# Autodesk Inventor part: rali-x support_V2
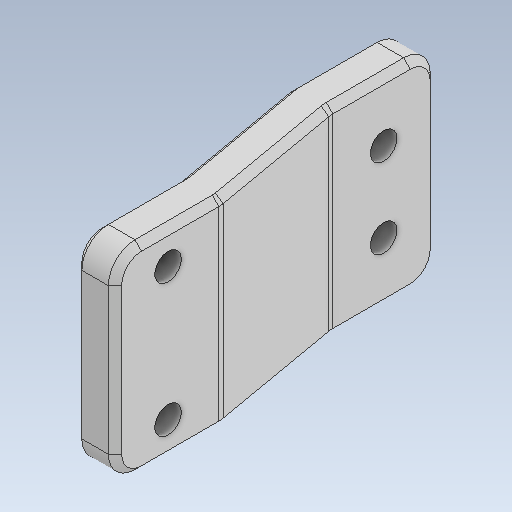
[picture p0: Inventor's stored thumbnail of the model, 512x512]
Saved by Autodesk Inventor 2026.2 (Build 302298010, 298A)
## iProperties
Created: 2026-04
Part Number: rali-x support_V2
Material: 일반
Document SubType Name: Modeling
Designer: khw
Density: 1 g/cm^3
Appearance: 기본값
Author: khw
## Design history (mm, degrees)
sketch "스케치1"
  geometry: L1 (0, 0)-(0, -16); L2 (0, -16)-(3.5, -36); L3 (3.5, -52)-(9.5, -52); L4 (9.5, -52)-(9.5, -36); L5 (9.5, -36)-(6, -16); L6 (6, -16)-(6, 0); L7 (6, 0)-(0, 0); L8 (0, -16)-(6, -16); L9 (3.5, -36)-(9.5, -36); L10 (3.5, -36)-(3.5, -52); 2 further points
  constraints: 20 end point, 4 parallel, 2 midpoint, 2 perpendicular, 1 vertical
  dimensions: "d0" = 6 distance from line of L6 point (0, -8); "d2" = 20 vertical distance of L1.end L2.end; "d3" = 6 distance from line of point (9.5, -44) L10; "d4" = 3.5 horizontal distance of L2.end L1.end; "d5" = 16 distance between parallel lines of L8 L7; "d6" = 16 distance of L3.end L4.end
extrude "돌출1" new body sketch "스케치1" distance "d7" = 30; taper "d8" = 0 deg
sketch "스케치2"
  geometry: L1 (0, 0)-(16, 0) reference; L2 (16, 0)-(16, 30) reference; L3 (0, 30)-(16, 30) reference; L4 (0, 0)-(0, 30) reference; L5 (-36, 0)-(-20, 0) reference; L6 (-20, 0)-(-20, 30) reference; L7 (-36, 30)-(-20, 30) reference; L8 (-36, 0)-(-36, 30) reference; L9 (-28, 0)-(-28, 30); L10 (8, 0)-(8, 30); L11 (16, 15)-(-36, 15); L12 (0, 0)-(-20, 0) reference; L13 (-20, 0)-(-20, 30) reference; L14 (0, 30)-(-20, 30) reference; L15 (0, 0)-(0, 30) reference; L16 (-17, 3)-(-3, 3); L17 (-3, 3)-(-3, 27); L18 (-3, 27)-(-17, 27); L19 (-17, 27)-(-17, 3); L20 (-3, 23.031)-(-14.685, 3); L21 (-17, 6.969)-(-5.315, 27); L22 (-14.685, 27)-(-3, 6.969); L23 (-5.315, 3)-(-17, 23.031); L24 (-17, 17)-(-3, 17); L25 (-3, 13)-(-7.048, 13); L26 (-7.048, 13)-(-17, 13); L27 (-3, 27)-(-17, 3); L28 (-3, 3)-(-17, 27); C1 r 2 at (8, 5); C2 r 2 at (-28, 9); C3 r 2 at (-28, 21); C4 r 2 at (8, 25); 8 further points
  constraints: 32 end point, 17 point on line, 7 midpoint, 4 centre point, 4 parallel, 2 perpendicular, 2 symmetric about line, 5 other
  dimensions: "d9" = 4 diameter of C1; "d10" = 10 distance from line of L11 C1.centre; "d11" = 4 diameter of C2; "d12" = 6 distance from line of L11 C2.centre; "d13" = 4 distance between parallel lines of L23 L22; "d15" = 4 distance between parallel lines of L25 L24; "d16" = 4 distance between parallel lines of L21 L20; "d17" = 2 distance between parallel lines of L21 L27; "d18" = 3 distance from line of L14 point (-10, 27); "d19" = 2 distance between parallel lines of L23 L28; "d20" = 2 distance between parallel lines of L11 L26
extrude "돌출2" cut sketch "스케치2" extent not by distance; stored distance "d21" = 0; taper "d22" = 0 deg
fillet "모깎기1" dims "d23" = 4
chamfer "모따기1" distance "d24" = 1; stored, may be unused: second distance "d25" = 2, angle "d26" = 45 deg
node "솔리드1"
node "투영된 루프1"
node "투영된 루프2"
node "투영된 루프3"
